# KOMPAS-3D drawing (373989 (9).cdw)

Referenced files: Спецификация.cdw
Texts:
  ТМАШ.СК-4.34-4-4
  Коробка передач комбайна СК-4 (фрагмент)
  Текст на чертеже
  Размерные надписи
  Шероховатость
  Линия-выноска #1
  Линия-выноска #2
  Линия-выноска #3
  Отклонения формы и база
  Заголовок таблицы
  Ячейка таблицы
  Стрелка вида
  Обозначение изменения
  Фигурная скобка
  Номер узла
  Марка координационной оси
  VRCB
  Выносная надпись
  Обозначение узла
  Марка/позиционное обозначение с линией-выноской
  Марка/позиционное обозначение на линии
  Марка/позиционное обозначение без линии-выноски
  Документация
  ТМАШ.СК-4.34-4-4 СБ
  Сборочный чертеж
  Шестерня
  Распорная втулка
  Ось
  Олейник
  ЧГАА Кафедра
  технологии машиностроения
  группа Т-51
  Коробка передач
  комбайна СК-4
  (фрагмент)
  Подшипник шариковый
  ГОСТ 8338-75
  Кольцо 1А72
  ТМАШ.СК-4.60637
  ТМАШ.СК-4.60640
  ТМАШ.СК-4.60672
  ТМАШ.СК-4.60681
  ТМАШ.СК-4.61208
  Стандартные изделия
  радиальный 207
  ТМАШ.СК-4.34-4-4-
Dimensions and other numbers on the sheet: 7; 1; 2; 3; 4; 5; 9; 10; 0; 6; 8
